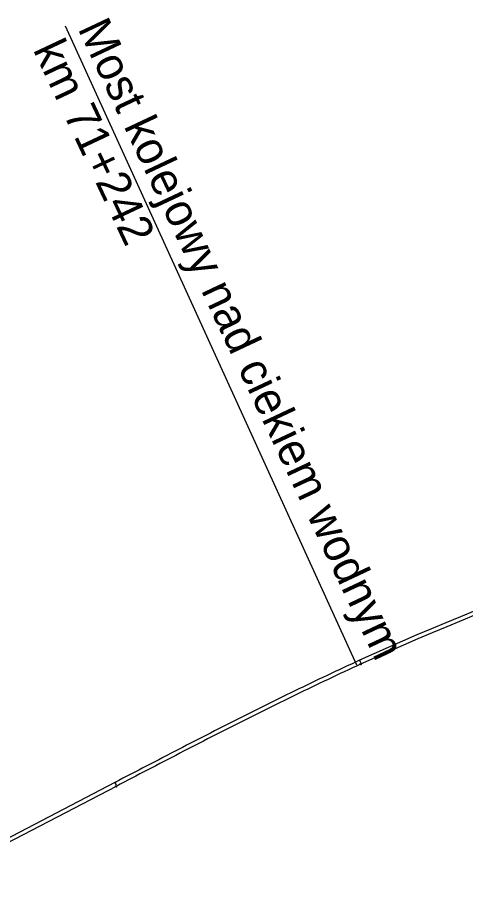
# Model space of a CAD drawing. Extents: x 6540402 to 6566579, y 5525343 to 5532423.
# Drawn here: x 6547686 to 6548161, y 5526559 to 5527495 of the extents above; entities that cross this region are included whole.
import ezdxf

# ---------------------------------------------------------------- set-up
doc = ezdxf.new("R2010")
doc.units = 0
for name, color, linetype in [('IR_ps_geometria', 7, 'Continuous'), ('TOR_PS_OPIS_T-opisy dodatkowe', 7, 'Continuous'), ('TOR_PS_OPIS_T-symbole geometrii', 7, 'Continuous'), ('TOR_PS_T-tory projektowane', 7, 'Continuous')]:
    doc.layers.add(name, color=color, linetype=linetype)

msp = doc.modelspace()

# ---------------------------------------------------------------- linework, layer by layer
at = {"layer": 'IR_ps_geometria'}
for points in [[(6548049.46, 5526808.53), (6548049.56, 5526808.3), (6548049.59, 5526808.31), (6548049.62, 5526808.32), (6548049.66, 5526808.32), (6548049.69, 5526808.32), (6548049.72, 5526808.32), (6548049.75, 5526808.31), (6548049.78, 5526808.29), (6548049.81, 5526808.28), (6548049.84, 5526808.26), (6548049.86, 5526808.23), (6548049.88, 5526808.2), (6548049.89, 5526808.18), (6548049.9, 5526808.15), (6548049.91, 5526808.11), (6548049.91, 5526808.08), (6548049.91, 5526808.05), (6548049.91, 5526808.02), (6548049.9, 5526807.98), (6548049.89, 5526807.95), (6548049.87, 5526807.93), (6548049.85, 5526807.9), (6548049.82, 5526807.88), (6548049.8, 5526807.86), (6548049.77, 5526807.84), (6548049.74, 5526807.83), (6548049.71, 5526807.83), (6548049.67, 5526807.82), (6548049.64, 5526807.82), (6548049.61, 5526807.83), (6548049.58, 5526807.84), (6548049.55, 5526807.85), (6548049.52, 5526807.87), (6548049.49, 5526807.89), (6548049.47, 5526807.91), (6548049.45, 5526807.94), (6548049.44, 5526807.97), (6548049.43, 5526808), (6548049.42, 5526808.03), (6548049.42, 5526808.06), (6548049.42, 5526808.1), (6548049.42, 5526808.13), (6548049.43, 5526808.16), (6548049.44, 5526808.19), (6548049.46, 5526808.22), (6548049.48, 5526808.24), (6548049.51, 5526808.26), (6548049.53, 5526808.28), (6548049.56, 5526808.3), (6548049.35, 5526808.75), (6548049.32, 5526808.74), (6548049.29, 5526808.74), (6548049.26, 5526808.73), (6548049.23, 5526808.73), (6548049.19, 5526808.74), (6548049.16, 5526808.75), (6548049.13, 5526808.76), (6548049.1, 5526808.78), (6548049.08, 5526808.8), (6548049.06, 5526808.82), (6548049.04, 5526808.85), (6548049.02, 5526808.88), (6548049.01, 5526808.91), (6548049, 5526808.94), (6548049, 5526808.97), (6548049, 5526809.01), (6548049.01, 5526809.04), (6548049.01, 5526809.07), (6548049.03, 5526809.1), (6548049.05, 5526809.13), (6548049.07, 5526809.15), (6548049.09, 5526809.17), (6548049.12, 5526809.19), (6548049.15, 5526809.21), (6548049.18, 5526809.22), (6548049.21, 5526809.23), (6548049.24, 5526809.23), (6548049.27, 5526809.23), (6548049.31, 5526809.23), (6548049.34, 5526809.22), (6548049.37, 5526809.2), (6548049.39, 5526809.19), (6548049.42, 5526809.16), (6548049.44, 5526809.14), (6548049.46, 5526809.11), (6548049.48, 5526809.09), (6548049.49, 5526809.05), (6548049.5, 5526809.02), (6548049.5, 5526808.99), (6548049.5, 5526808.96), (6548049.49, 5526808.93), (6548049.48, 5526808.89), (6548049.47, 5526808.86), (6548049.45, 5526808.84), (6548049.43, 5526808.81), (6548049.41, 5526808.79), (6548049.38, 5526808.77), (6548049.35, 5526808.75)], [(6548049.46, 5526808.53), (6548049.56, 5526808.3), (6548049.59, 5526808.31), (6548049.62, 5526808.32), (6548049.66, 5526808.32), (6548049.69, 5526808.32), (6548049.72, 5526808.32), (6548049.75, 5526808.31), (6548049.78, 5526808.29), (6548049.81, 5526808.28), (6548049.84, 5526808.26), (6548049.86, 5526808.23), (6548049.88, 5526808.2), (6548049.89, 5526808.18), (6548049.9, 5526808.15), (6548049.91, 5526808.11), (6548049.91, 5526808.08), (6548049.91, 5526808.05), (6548049.91, 5526808.02), (6548049.9, 5526807.98), (6548049.89, 5526807.95), (6548049.87, 5526807.93), (6548049.85, 5526807.9), (6548049.82, 5526807.88), (6548049.8, 5526807.86), (6548049.77, 5526807.84), (6548049.74, 5526807.83), (6548049.71, 5526807.83), (6548049.67, 5526807.82), (6548049.64, 5526807.82), (6548049.61, 5526807.83), (6548049.58, 5526807.84), (6548049.55, 5526807.85), (6548049.52, 5526807.87), (6548049.49, 5526807.89), (6548049.47, 5526807.91), (6548049.45, 5526807.94), (6548049.44, 5526807.97), (6548049.43, 5526808), (6548049.42, 5526808.03), (6548049.42, 5526808.06), (6548049.42, 5526808.1), (6548049.42, 5526808.13), (6548049.43, 5526808.16), (6548049.44, 5526808.19), (6548049.46, 5526808.22), (6548049.48, 5526808.24), (6548049.51, 5526808.26), (6548049.53, 5526808.28), (6548049.56, 5526808.3), (6548049.35, 5526808.75), (6548049.32, 5526808.74), (6548049.29, 5526808.74), (6548049.26, 5526808.73), (6548049.23, 5526808.73), (6548049.19, 5526808.74), (6548049.16, 5526808.75), (6548049.13, 5526808.76), (6548049.1, 5526808.78), (6548049.08, 5526808.8), (6548049.06, 5526808.82), (6548049.04, 5526808.85), (6548049.02, 5526808.88), (6548049.01, 5526808.91), (6548049, 5526808.94), (6548049, 5526808.97), (6548049, 5526809.01), (6548049.01, 5526809.04), (6548049.01, 5526809.07), (6548049.03, 5526809.1), (6548049.05, 5526809.13), (6548049.07, 5526809.15), (6548049.09, 5526809.17), (6548049.12, 5526809.19), (6548049.15, 5526809.21), (6548049.18, 5526809.22), (6548049.21, 5526809.23), (6548049.24, 5526809.23), (6548049.27, 5526809.23), (6548049.31, 5526809.23), (6548049.34, 5526809.22), (6548049.37, 5526809.2), (6548049.39, 5526809.19), (6548049.42, 5526809.16), (6548049.44, 5526809.14), (6548049.46, 5526809.11), (6548049.48, 5526809.09), (6548049.49, 5526809.05), (6548049.5, 5526809.02), (6548049.5, 5526808.99), (6548049.5, 5526808.96), (6548049.49, 5526808.93), (6548049.48, 5526808.89), (6548049.47, 5526808.86), (6548049.45, 5526808.84), (6548049.43, 5526808.81), (6548049.41, 5526808.79), (6548049.38, 5526808.77), (6548049.35, 5526808.75)], [(6548049.46, 5526808.53), (6548049.56, 5526808.3), (6548049.59, 5526808.31), (6548049.62, 5526808.32), (6548049.66, 5526808.32), (6548049.69, 5526808.32), (6548049.72, 5526808.32), (6548049.75, 5526808.31), (6548049.78, 5526808.29), (6548049.81, 5526808.28), (6548049.84, 5526808.26), (6548049.86, 5526808.23), (6548049.88, 5526808.2), (6548049.89, 5526808.18), (6548049.9, 5526808.15), (6548049.91, 5526808.11), (6548049.91, 5526808.08), (6548049.91, 5526808.05), (6548049.91, 5526808.02), (6548049.9, 5526807.98), (6548049.89, 5526807.95), (6548049.87, 5526807.93), (6548049.85, 5526807.9), (6548049.82, 5526807.88), (6548049.8, 5526807.86), (6548049.77, 5526807.84), (6548049.74, 5526807.83), (6548049.71, 5526807.83), (6548049.67, 5526807.82), (6548049.64, 5526807.82), (6548049.61, 5526807.83), (6548049.58, 5526807.84), (6548049.55, 5526807.85), (6548049.52, 5526807.87), (6548049.49, 5526807.89), (6548049.47, 5526807.91), (6548049.45, 5526807.94), (6548049.44, 5526807.97), (6548049.43, 5526808), (6548049.42, 5526808.03), (6548049.42, 5526808.06), (6548049.42, 5526808.1), (6548049.42, 5526808.13), (6548049.43, 5526808.16), (6548049.44, 5526808.19), (6548049.46, 5526808.22), (6548049.48, 5526808.24), (6548049.51, 5526808.26), (6548049.53, 5526808.28), (6548049.56, 5526808.3), (6548049.35, 5526808.75), (6548049.32, 5526808.74), (6548049.29, 5526808.74), (6548049.26, 5526808.73), (6548049.23, 5526808.73), (6548049.19, 5526808.74), (6548049.16, 5526808.75), (6548049.13, 5526808.76), (6548049.1, 5526808.78), (6548049.08, 5526808.8), (6548049.06, 5526808.82), (6548049.04, 5526808.85), (6548049.02, 5526808.88), (6548049.01, 5526808.91), (6548049, 5526808.94), (6548049, 5526808.97), (6548049, 5526809.01), (6548049.01, 5526809.04), (6548049.01, 5526809.07), (6548049.03, 5526809.1), (6548049.05, 5526809.13), (6548049.07, 5526809.15), (6548049.09, 5526809.17), (6548049.12, 5526809.19), (6548049.15, 5526809.21), (6548049.18, 5526809.22), (6548049.21, 5526809.23), (6548049.24, 5526809.23), (6548049.27, 5526809.23), (6548049.31, 5526809.23), (6548049.34, 5526809.22), (6548049.37, 5526809.2), (6548049.39, 5526809.19), (6548049.42, 5526809.16), (6548049.44, 5526809.14), (6548049.46, 5526809.11), (6548049.48, 5526809.09), (6548049.49, 5526809.05), (6548049.5, 5526809.02), (6548049.5, 5526808.99), (6548049.5, 5526808.96), (6548049.49, 5526808.93), (6548049.48, 5526808.89), (6548049.47, 5526808.86), (6548049.45, 5526808.84), (6548049.43, 5526808.81), (6548049.41, 5526808.79), (6548049.38, 5526808.77), (6548049.35, 5526808.75)], [(6548049.46, 5526808.53), (6548049.56, 5526808.3), (6548049.59, 5526808.31), (6548049.62, 5526808.32), (6548049.66, 5526808.32), (6548049.69, 5526808.32), (6548049.72, 5526808.32), (6548049.75, 5526808.31), (6548049.78, 5526808.29), (6548049.81, 5526808.28), (6548049.84, 5526808.26), (6548049.86, 5526808.23), (6548049.88, 5526808.2), (6548049.89, 5526808.18), (6548049.9, 5526808.15), (6548049.91, 5526808.11), (6548049.91, 5526808.08), (6548049.91, 5526808.05), (6548049.91, 5526808.02), (6548049.9, 5526807.98), (6548049.89, 5526807.95), (6548049.87, 5526807.93), (6548049.85, 5526807.9), (6548049.82, 5526807.88), (6548049.8, 5526807.86), (6548049.77, 5526807.84), (6548049.74, 5526807.83), (6548049.71, 5526807.83), (6548049.67, 5526807.82), (6548049.64, 5526807.82), (6548049.61, 5526807.83), (6548049.58, 5526807.84), (6548049.55, 5526807.85), (6548049.52, 5526807.87), (6548049.49, 5526807.89), (6548049.47, 5526807.91), (6548049.45, 5526807.94), (6548049.44, 5526807.97), (6548049.43, 5526808), (6548049.42, 5526808.03), (6548049.42, 5526808.06), (6548049.42, 5526808.1), (6548049.42, 5526808.13), (6548049.43, 5526808.16), (6548049.44, 5526808.19), (6548049.46, 5526808.22), (6548049.48, 5526808.24), (6548049.51, 5526808.26), (6548049.53, 5526808.28), (6548049.56, 5526808.3), (6548049.35, 5526808.75), (6548049.32, 5526808.74), (6548049.29, 5526808.74), (6548049.26, 5526808.73), (6548049.23, 5526808.73), (6548049.19, 5526808.74), (6548049.16, 5526808.75), (6548049.13, 5526808.76), (6548049.1, 5526808.78), (6548049.08, 5526808.8), (6548049.06, 5526808.82), (6548049.04, 5526808.85), (6548049.02, 5526808.88), (6548049.01, 5526808.91), (6548049, 5526808.94), (6548049, 5526808.97), (6548049, 5526809.01), (6548049.01, 5526809.04), (6548049.01, 5526809.07), (6548049.03, 5526809.1), (6548049.05, 5526809.13), (6548049.07, 5526809.15), (6548049.09, 5526809.17), (6548049.12, 5526809.19), (6548049.15, 5526809.21), (6548049.18, 5526809.22), (6548049.21, 5526809.23), (6548049.24, 5526809.23), (6548049.27, 5526809.23), (6548049.31, 5526809.23), (6548049.34, 5526809.22), (6548049.37, 5526809.2), (6548049.39, 5526809.19), (6548049.42, 5526809.16), (6548049.44, 5526809.14), (6548049.46, 5526809.11), (6548049.48, 5526809.09), (6548049.49, 5526809.05), (6548049.5, 5526809.02), (6548049.5, 5526808.99), (6548049.5, 5526808.96), (6548049.49, 5526808.93), (6548049.48, 5526808.89), (6548049.47, 5526808.86), (6548049.45, 5526808.84), (6548049.43, 5526808.81), (6548049.41, 5526808.79), (6548049.38, 5526808.77), (6548049.35, 5526808.75)], [(6547790.06, 5526678.94), (6547790.17, 5526678.72), (6547790.2, 5526678.73), (6547790.24, 5526678.74), (6547790.27, 5526678.75), (6547790.3, 5526678.75), (6547790.33, 5526678.74), (6547790.37, 5526678.74), (6547790.4, 5526678.72), (6547790.42, 5526678.71), (6547790.45, 5526678.69), (6547790.47, 5526678.67), (6547790.5, 5526678.64), (6547790.51, 5526678.61), (6547790.53, 5526678.58), (6547790.53, 5526678.55), (6547790.54, 5526678.52), (6547790.54, 5526678.49), (6547790.54, 5526678.45), (6547790.53, 5526678.42), (6547790.52, 5526678.39), (6547790.5, 5526678.36), (6547790.48, 5526678.34), (6547790.46, 5526678.31), (6547790.43, 5526678.29), (6547790.41, 5526678.28), (6547790.38, 5526678.26), (6547790.34, 5526678.25), (6547790.31, 5526678.25), (6547790.28, 5526678.25), (6547790.25, 5526678.25), (6547790.22, 5526678.26), (6547790.18, 5526678.27), (6547790.16, 5526678.29), (6547790.13, 5526678.31), (6547790.11, 5526678.33), (6547790.09, 5526678.35), (6547790.07, 5526678.38), (6547790.06, 5526678.41), (6547790.05, 5526678.44), (6547790.04, 5526678.47), (6547790.04, 5526678.51), (6547790.04, 5526678.54), (6547790.05, 5526678.57), (6547790.06, 5526678.6), (6547790.08, 5526678.63), (6547790.1, 5526678.66), (6547790.12, 5526678.68), (6547790.15, 5526678.7), (6547790.17, 5526678.72), (6547789.94, 5526679.16), (6547789.91, 5526679.15), (6547789.88, 5526679.14), (6547789.85, 5526679.13), (6547789.82, 5526679.13), (6547789.78, 5526679.14), (6547789.75, 5526679.15), (6547789.72, 5526679.16), (6547789.69, 5526679.17), (6547789.67, 5526679.19), (6547789.64, 5526679.21), (6547789.62, 5526679.24), (6547789.61, 5526679.27), (6547789.59, 5526679.3), (6547789.58, 5526679.33), (6547789.58, 5526679.36), (6547789.58, 5526679.39), (6547789.58, 5526679.43), (6547789.59, 5526679.46), (6547789.6, 5526679.49), (6547789.62, 5526679.52), (6547789.64, 5526679.54), (6547789.66, 5526679.57), (6547789.68, 5526679.59), (6547789.71, 5526679.61), (6547789.74, 5526679.62), (6547789.77, 5526679.63), (6547789.81, 5526679.63), (6547789.84, 5526679.63), (6547789.87, 5526679.63), (6547789.9, 5526679.62), (6547789.93, 5526679.61), (6547789.96, 5526679.59), (6547789.99, 5526679.58), (6547790.01, 5526679.55), (6547790.03, 5526679.53), (6547790.05, 5526679.5), (6547790.06, 5526679.47), (6547790.07, 5526679.44), (6547790.08, 5526679.41), (6547790.08, 5526679.37), (6547790.07, 5526679.34), (6547790.07, 5526679.31), (6547790.05, 5526679.28), (6547790.04, 5526679.25), (6547790.02, 5526679.22), (6547790, 5526679.2), (6547789.97, 5526679.18), (6547789.94, 5526679.16)], [(6547790.06, 5526678.94), (6547790.17, 5526678.72), (6547790.2, 5526678.73), (6547790.24, 5526678.74), (6547790.27, 5526678.75), (6547790.3, 5526678.75), (6547790.33, 5526678.74), (6547790.37, 5526678.74), (6547790.4, 5526678.72), (6547790.42, 5526678.71), (6547790.45, 5526678.69), (6547790.47, 5526678.67), (6547790.5, 5526678.64), (6547790.51, 5526678.61), (6547790.53, 5526678.58), (6547790.53, 5526678.55), (6547790.54, 5526678.52), (6547790.54, 5526678.49), (6547790.54, 5526678.45), (6547790.53, 5526678.42), (6547790.52, 5526678.39), (6547790.5, 5526678.36), (6547790.48, 5526678.34), (6547790.46, 5526678.31), (6547790.43, 5526678.29), (6547790.41, 5526678.28), (6547790.38, 5526678.26), (6547790.34, 5526678.25), (6547790.31, 5526678.25), (6547790.28, 5526678.25), (6547790.25, 5526678.25), (6547790.22, 5526678.26), (6547790.18, 5526678.27), (6547790.16, 5526678.29), (6547790.13, 5526678.31), (6547790.11, 5526678.33), (6547790.09, 5526678.35), (6547790.07, 5526678.38), (6547790.06, 5526678.41), (6547790.05, 5526678.44), (6547790.04, 5526678.47), (6547790.04, 5526678.51), (6547790.04, 5526678.54), (6547790.05, 5526678.57), (6547790.06, 5526678.6), (6547790.08, 5526678.63), (6547790.1, 5526678.66), (6547790.12, 5526678.68), (6547790.15, 5526678.7), (6547790.17, 5526678.72), (6547789.94, 5526679.16), (6547789.91, 5526679.15), (6547789.88, 5526679.14), (6547789.85, 5526679.13), (6547789.82, 5526679.13), (6547789.78, 5526679.14), (6547789.75, 5526679.15), (6547789.72, 5526679.16), (6547789.69, 5526679.17), (6547789.67, 5526679.19), (6547789.64, 5526679.21), (6547789.62, 5526679.24), (6547789.61, 5526679.27), (6547789.59, 5526679.3), (6547789.58, 5526679.33), (6547789.58, 5526679.36), (6547789.58, 5526679.39), (6547789.58, 5526679.43), (6547789.59, 5526679.46), (6547789.6, 5526679.49), (6547789.62, 5526679.52), (6547789.64, 5526679.54), (6547789.66, 5526679.57), (6547789.68, 5526679.59), (6547789.71, 5526679.61), (6547789.74, 5526679.62), (6547789.77, 5526679.63), (6547789.81, 5526679.63), (6547789.84, 5526679.63), (6547789.87, 5526679.63), (6547789.9, 5526679.62), (6547789.93, 5526679.61), (6547789.96, 5526679.59), (6547789.99, 5526679.58), (6547790.01, 5526679.55), (6547790.03, 5526679.53), (6547790.05, 5526679.5), (6547790.06, 5526679.47), (6547790.07, 5526679.44), (6547790.08, 5526679.41), (6547790.08, 5526679.37), (6547790.07, 5526679.34), (6547790.07, 5526679.31), (6547790.05, 5526679.28), (6547790.04, 5526679.25), (6547790.02, 5526679.22), (6547790, 5526679.2), (6547789.97, 5526679.18), (6547789.94, 5526679.16)], [(6547790.06, 5526678.94), (6547790.17, 5526678.72), (6547790.2, 5526678.73), (6547790.24, 5526678.74), (6547790.27, 5526678.75), (6547790.3, 5526678.75), (6547790.33, 5526678.74), (6547790.37, 5526678.74), (6547790.4, 5526678.72), (6547790.42, 5526678.71), (6547790.45, 5526678.69), (6547790.47, 5526678.67), (6547790.5, 5526678.64), (6547790.51, 5526678.61), (6547790.53, 5526678.58), (6547790.53, 5526678.55), (6547790.54, 5526678.52), (6547790.54, 5526678.49), (6547790.54, 5526678.45), (6547790.53, 5526678.42), (6547790.52, 5526678.39), (6547790.5, 5526678.36), (6547790.48, 5526678.34), (6547790.46, 5526678.31), (6547790.43, 5526678.29), (6547790.41, 5526678.28), (6547790.38, 5526678.26), (6547790.34, 5526678.25), (6547790.31, 5526678.25), (6547790.28, 5526678.25), (6547790.25, 5526678.25), (6547790.22, 5526678.26), (6547790.18, 5526678.27), (6547790.16, 5526678.29), (6547790.13, 5526678.31), (6547790.11, 5526678.33), (6547790.09, 5526678.35), (6547790.07, 5526678.38), (6547790.06, 5526678.41), (6547790.05, 5526678.44), (6547790.04, 5526678.47), (6547790.04, 5526678.51), (6547790.04, 5526678.54), (6547790.05, 5526678.57), (6547790.06, 5526678.6), (6547790.08, 5526678.63), (6547790.1, 5526678.66), (6547790.12, 5526678.68), (6547790.15, 5526678.7), (6547790.17, 5526678.72), (6547789.94, 5526679.16), (6547789.91, 5526679.15), (6547789.88, 5526679.14), (6547789.85, 5526679.13), (6547789.82, 5526679.13), (6547789.78, 5526679.14), (6547789.75, 5526679.15), (6547789.72, 5526679.16), (6547789.69, 5526679.17), (6547789.67, 5526679.19), (6547789.64, 5526679.21), (6547789.62, 5526679.24), (6547789.61, 5526679.27), (6547789.59, 5526679.3), (6547789.58, 5526679.33), (6547789.58, 5526679.36), (6547789.58, 5526679.39), (6547789.58, 5526679.43), (6547789.59, 5526679.46), (6547789.6, 5526679.49), (6547789.62, 5526679.52), (6547789.64, 5526679.54), (6547789.66, 5526679.57), (6547789.68, 5526679.59), (6547789.71, 5526679.61), (6547789.74, 5526679.62), (6547789.77, 5526679.63), (6547789.81, 5526679.63), (6547789.84, 5526679.63), (6547789.87, 5526679.63), (6547789.9, 5526679.62), (6547789.93, 5526679.61), (6547789.96, 5526679.59), (6547789.99, 5526679.58), (6547790.01, 5526679.55), (6547790.03, 5526679.53), (6547790.05, 5526679.5), (6547790.06, 5526679.47), (6547790.07, 5526679.44), (6547790.08, 5526679.41), (6547790.08, 5526679.37), (6547790.07, 5526679.34), (6547790.07, 5526679.31), (6547790.05, 5526679.28), (6547790.04, 5526679.25), (6547790.02, 5526679.22), (6547790, 5526679.2), (6547789.97, 5526679.18), (6547789.94, 5526679.16)], [(6547790.06, 5526678.94), (6547790.17, 5526678.72), (6547790.2, 5526678.73), (6547790.24, 5526678.74), (6547790.27, 5526678.75), (6547790.3, 5526678.75), (6547790.33, 5526678.74), (6547790.37, 5526678.74), (6547790.4, 5526678.72), (6547790.42, 5526678.71), (6547790.45, 5526678.69), (6547790.47, 5526678.67), (6547790.5, 5526678.64), (6547790.51, 5526678.61), (6547790.53, 5526678.58), (6547790.53, 5526678.55), (6547790.54, 5526678.52), (6547790.54, 5526678.49), (6547790.54, 5526678.45), (6547790.53, 5526678.42), (6547790.52, 5526678.39), (6547790.5, 5526678.36), (6547790.48, 5526678.34), (6547790.46, 5526678.31), (6547790.43, 5526678.29), (6547790.41, 5526678.28), (6547790.38, 5526678.26), (6547790.34, 5526678.25), (6547790.31, 5526678.25), (6547790.28, 5526678.25), (6547790.25, 5526678.25), (6547790.22, 5526678.26), (6547790.18, 5526678.27), (6547790.16, 5526678.29), (6547790.13, 5526678.31), (6547790.11, 5526678.33), (6547790.09, 5526678.35), (6547790.07, 5526678.38), (6547790.06, 5526678.41), (6547790.05, 5526678.44), (6547790.04, 5526678.47), (6547790.04, 5526678.51), (6547790.04, 5526678.54), (6547790.05, 5526678.57), (6547790.06, 5526678.6), (6547790.08, 5526678.63), (6547790.1, 5526678.66), (6547790.12, 5526678.68), (6547790.15, 5526678.7), (6547790.17, 5526678.72), (6547789.94, 5526679.16), (6547789.91, 5526679.15), (6547789.88, 5526679.14), (6547789.85, 5526679.13), (6547789.82, 5526679.13), (6547789.78, 5526679.14), (6547789.75, 5526679.15), (6547789.72, 5526679.16), (6547789.69, 5526679.17), (6547789.67, 5526679.19), (6547789.64, 5526679.21), (6547789.62, 5526679.24), (6547789.61, 5526679.27), (6547789.59, 5526679.3), (6547789.58, 5526679.33), (6547789.58, 5526679.36), (6547789.58, 5526679.39), (6547789.58, 5526679.43), (6547789.59, 5526679.46), (6547789.6, 5526679.49), (6547789.62, 5526679.52), (6547789.64, 5526679.54), (6547789.66, 5526679.57), (6547789.68, 5526679.59), (6547789.71, 5526679.61), (6547789.74, 5526679.62), (6547789.77, 5526679.63), (6547789.81, 5526679.63), (6547789.84, 5526679.63), (6547789.87, 5526679.63), (6547789.9, 5526679.62), (6547789.93, 5526679.61), (6547789.96, 5526679.59), (6547789.99, 5526679.58), (6547790.01, 5526679.55), (6547790.03, 5526679.53), (6547790.05, 5526679.5), (6547790.06, 5526679.47), (6547790.07, 5526679.44), (6547790.08, 5526679.41), (6547790.08, 5526679.37), (6547790.07, 5526679.34), (6547790.07, 5526679.31), (6547790.05, 5526679.28), (6547790.04, 5526679.25), (6547790.02, 5526679.22), (6547790, 5526679.2), (6547789.97, 5526679.18), (6547789.94, 5526679.16)]]:
    msp.add_lwpolyline(points, close=True, dxfattribs=at)
at = {"layer": 'TOR_PS_OPIS_T-opisy dodatkowe'}
msp.add_line((6547735.94, 5527485.84), (6548045.21, 5526808.07), dxfattribs=at)
at = {"layer": 'TOR_PS_OPIS_T-symbole geometrii'}
for p, q in [((6548048.33, 5526812.68), (6548048.23, 5526811.69)), ((6548048.33, 5526812.68), (6548049.58, 5526809.96)), ((6548048.33, 5526812.68), (6548049.14, 5526812.1)), ((6547788.93, 5526683.09), (6547788.89, 5526682.09)), ((6547788.93, 5526683.09), (6547790.32, 5526680.43)), ((6547788.93, 5526683.09), (6547789.78, 5526682.55))]:
    msp.add_line(p, q, dxfattribs=at)
at = {"layer": 'TOR_PS_T-tory projektowane'}
for p, q in [((6547790.06, 5526678.94), (6546521.11, 5526017.4)), ((6547788.93, 5526683.09), (6546521.48, 5526022.34))]:
    msp.add_line(p, q, dxfattribs=at)
for points in [[(6548048.33, 5526812.68), (6548044.01, 5526810.7), (6548039.69, 5526808.72), (6548035.37, 5526806.72), (6548031.06, 5526804.72), (6548026.75, 5526802.71), (6548022.44, 5526800.7), (6548018.14, 5526798.67), (6548013.84, 5526796.64), (6548009.55, 5526794.61), (6548005.25, 5526792.57), (6548000.96, 5526790.52), (6547996.67, 5526788.47), (6547992.39, 5526786.41), (6547988.11, 5526784.35), (6547983.83, 5526782.28), (6547979.55, 5526780.2), (6547975.27, 5526778.12), (6547971, 5526776.03), (6547966.73, 5526773.94), (6547962.47, 5526771.85), (6547958.2, 5526769.74), (6547953.94, 5526767.64), (6547949.68, 5526765.53), (6547945.42, 5526763.41), (6547941.17, 5526761.29), (6547936.91, 5526759.17), (6547932.66, 5526757.04), (6547928.41, 5526754.91), (6547924.16, 5526752.78), (6547919.92, 5526750.64), (6547915.68, 5526748.49), (6547911.43, 5526746.35), (6547907.19, 5526744.2), (6547902.95, 5526742.04), (6547898.72, 5526739.89), (6547894.48, 5526737.73), (6547890.25, 5526735.56), (6547886.02, 5526733.4), (6547881.79, 5526731.23), (6547877.56, 5526729.06), (6547873.33, 5526726.89), (6547869.1, 5526724.71), (6547864.87, 5526722.53), (6547860.65, 5526720.36), (6547856.43, 5526718.17), (6547852.2, 5526715.99), (6547847.98, 5526713.8), (6547843.76, 5526711.62), (6547839.54, 5526709.43), (6547835.32, 5526707.24), (6547831.1, 5526705.05), (6547826.88, 5526702.86), (6547822.66, 5526700.66), (6547818.45, 5526698.47), (6547814.23, 5526696.27), (6547810.01, 5526694.08), (6547805.8, 5526691.88), (6547801.58, 5526689.68), (6547797.36, 5526687.49), (6547793.15, 5526685.29), (6547788.93, 5526683.09)], [(6548049.46, 5526808.53), (6548045.14, 5526806.55), (6548040.82, 5526804.56), (6548036.5, 5526802.56), (6548032.19, 5526800.56), (6548027.88, 5526798.55), (6548023.57, 5526796.54), (6548019.27, 5526794.52), (6548014.97, 5526792.49), (6548010.67, 5526790.46), (6548006.38, 5526788.42), (6548002.09, 5526786.37), (6547997.8, 5526784.32), (6547993.52, 5526782.26), (6547989.23, 5526780.19), (6547984.95, 5526778.12), (6547980.68, 5526776.05), (6547976.4, 5526773.97), (6547972.13, 5526771.88), (6547967.86, 5526769.79), (6547963.59, 5526767.69), (6547959.33, 5526765.59), (6547955.07, 5526763.49), (6547950.81, 5526761.38), (6547946.55, 5526759.26), (6547942.29, 5526757.14), (6547938.04, 5526755.02), (6547933.79, 5526752.89), (6547929.54, 5526750.76), (6547925.29, 5526748.62), (6547921.04, 5526746.49), (6547916.8, 5526744.34), (6547912.56, 5526742.2), (6547908.32, 5526740.05), (6547904.08, 5526737.89), (6547899.84, 5526735.74), (6547895.61, 5526733.58), (6547891.37, 5526731.41), (6547887.14, 5526729.25), (6547882.91, 5526727.08), (6547878.68, 5526724.91), (6547874.45, 5526722.74), (6547870.23, 5526720.56), (6547866, 5526718.38), (6547861.77, 5526716.21), (6547857.55, 5526714.02), (6547853.33, 5526711.84), (6547849.11, 5526709.65), (6547844.88, 5526707.47), (6547840.66, 5526705.28), (6547836.44, 5526703.09), (6547832.23, 5526700.9), (6547828.01, 5526698.71), (6547823.79, 5526696.51), (6547819.57, 5526694.32), (6547815.36, 5526692.12), (6547811.14, 5526689.93), (6547806.92, 5526687.73), (6547802.71, 5526685.53), (6547798.49, 5526683.34), (6547794.27, 5526681.14), (6547790.06, 5526678.94)]]:
    msp.add_lwpolyline(points, dxfattribs=at)
for centre, radius, start, end in [((6549214.77, 5524261.71), 2805, 103.69505, 114.57239), ((6549213.58, 5524262), 2800, 103.70034, 114.5671)]:
    msp.add_arc(centre, radius, start, end, dxfattribs=at)

# ---------------------------------------------------------------- texts
at = {"layer": 'TOR_PS_OPIS_T-opisy dodatkowe'}
for s, p in [('Most kolejowy nad ciekiem wodnym', (6547749.07, 5527483.12)), ('km 71+242', (6547701.58, 5527460.74))]:
    msp.add_text(s, height=35, rotation=295.22707, dxfattribs=at).set_placement(p)

doc.saveas('drawing.dxf')
